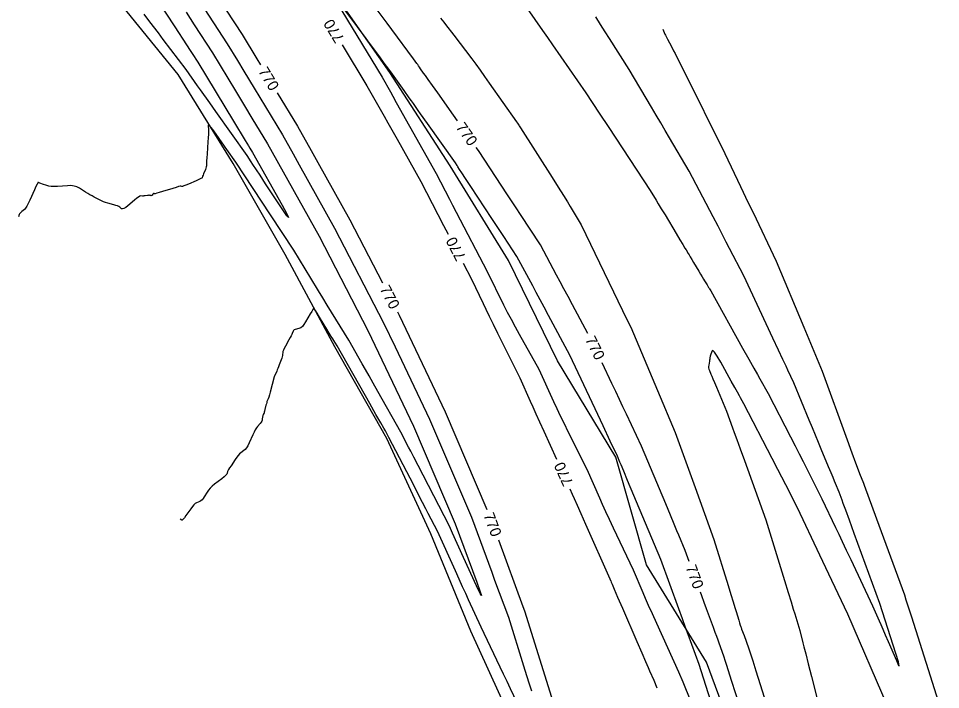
# Model space of a CAD drawing. Extents: x -26 to 1809989, y -25 to 828749.
# Drawn here: x 1809492.9 to 1809917.3, y 828203.8 to 828512.9 of the extents above; entities that cross this region are included whole.
import ezdxf

# ---------------------------------------------------------------- set-up
doc = ezdxf.new("R2010")
doc.units = 0
for name, color, linetype in [('DESIGN - CONTOURS - Index with Text', 7, 'Continuous'), ('DESIGN - CONTOURS - Intermediate with optional Text', 7, 'Continuous'), ('DESIGN - ROW - Slope Lines', 7, 'Continuous')]:
    doc.layers.add(name, color=color, linetype=linetype)

msp = doc.modelspace()

# ---------------------------------------------------------------- linework, layer by layer
at = {"layer": 'DESIGN - CONTOURS - Index with Text'}
for points in [[(1809549.23, 828574.97), (1809550.14, 828573.67), (1809554.39, 828567.6), (1809568.83, 828546.94), (1809584.94, 828522.18), (1809588.52, 828516.69), (1809595.77, 828505.55), (1809602.52, 828494.37), (1809604.26, 828491.5)], [(1809694.95, 828465.75), (1809693.1, 828468.36), (1809685.85, 828478.62), (1809683.41, 828482.08), (1809681.51, 828484.76), (1809680.17, 828486.66), (1809679.37, 828487.79), (1809677.98, 828489.76), (1809677.48, 828490.46), (1809677.03, 828491.1), (1809676.63, 828491.68), (1809676.27, 828492.18), (1809674.7, 828494.4), (1809664.78, 828507.8), (1809662.61, 828510.74), (1809660.36, 828513.79), (1809658.01, 828516.95), (1809655.58, 828520.24), (1809644.02, 828535.87), (1809638.31, 828543.4), (1809637.07, 828545.05), (1809635.97, 828546.5)], [(1809641.88, 828500.76), (1809653.29, 828481.93), (1809661.18, 828467.89), (1809662.91, 828464.8), (1809667.12, 828457.31), (1809678.07, 828437.79), (1809688.55, 828417.59), (1809690.67, 828413.5)], [(1809612.01, 828478.67), (1809621.31, 828463.29), (1809627.55, 828452.14), (1809630.69, 828446.52), (1809645.42, 828420.2), (1809660.41, 828391.19)], [(1809754.91, 828367.79), (1809747.87, 828381.02), (1809745.86, 828384.8), (1809743.97, 828388.35), (1809742.2, 828391.67), (1809740.55, 828394.76), (1809733.14, 828408.64), (1809723.96, 828422.63), (1809721.95, 828425.69), (1809719.85, 828428.89), (1809717.66, 828432.21), (1809715.39, 828435.66), (1809704.6, 828452.09), (1809703.6, 828453.5)], [(1809697.57, 828400.18), (1809701.37, 828392.86), (1809706.73, 828381.62), (1809708.01, 828378.96), (1809709.55, 828375.8), (1809711.35, 828372.14), (1809713.41, 828367.97), (1809723.63, 828347.38), (1809728.41, 828336.63), (1809729.57, 828334.04), (1809731, 828330.87), (1809732.71, 828327.12), (1809734.69, 828322.8), (1809740.59, 828309.93)], [(1809667.3, 828377.86), (1809668.09, 828376.33), (1809689.28, 828331.73), (1809708.53, 828286.78)], [(1809801.62, 828262.76), (1809799.73, 828267.94), (1809796.82, 828274.91), (1809795.97, 828276.93), (1809794.69, 828280), (1809792.97, 828284.12), (1809790.8, 828289.29), (1809779.69, 828315.87), (1809772.68, 828330.73), (1809771.14, 828334), (1809769.52, 828337.44), (1809767.82, 828341.05), (1809766.04, 828344.83), (1809761.55, 828354.35)], [(1809746.74, 828296.25), (1809747.76, 828293.88), (1809748.66, 828291.83), (1809749.98, 828288.82), (1809751.73, 828284.87), (1809753.91, 828279.96), (1809765.06, 828254.85), (1809765.29, 828254.31), (1809765.34, 828254.18), (1809765.41, 828254.02), (1809765.49, 828253.84), (1809765.72, 828253.31), (1809766.1, 828252.42), (1809767.09, 828250.12), (1809768.68, 828246.43), (1809770.88, 828241.33), (1809777.52, 828225.89), (1809779.76, 828220.71), (1809781.47, 828216.74), (1809782.67, 828213.99), (1809783.34, 828212.46), (1809785.29, 828208.16), (1809786.77, 828204.61)], [(1809713.76, 828272.72), (1809725.07, 828242.14), (1809725.84, 828240.05), (1809740.59, 828192.97), (1809743.73, 828180.77), (1809744.54, 828177.64)], [(1809837.62, 828153.6), (1809836.87, 828156.35), (1809836.16, 828159), (1809833.3, 828169.6), (1809823.06, 828201.85), (1809821.12, 828207.97), (1809819.69, 828212.48), (1809818.76, 828215.4), (1809818.35, 828216.71), (1809817.58, 828219.13), (1809815.38, 828225.13), (1809814.87, 828226.55), (1809814.26, 828228.22), (1809813.55, 828230.15), (1809812.75, 828232.34), (1809810.49, 828238.51), (1809809.58, 828241), (1809808.54, 828243.84), (1809807.37, 828247.04), (1809806.77, 828248.68)]]:
    msp.add_lwpolyline(points, dxfattribs=at)
at = {"layer": 'DESIGN - CONTOURS - Intermediate with optional Text'}
for points in [[(1809548.95, 828533.51), (1809564.88, 828509.02), (1809570.28, 828500.72), (1809571.91, 828498.22), (1809572.83, 828496.81), (1809575.44, 828492.79), (1809591.82, 828465.68), (1809597.22, 828456.75), (1809598.7, 828454.31), (1809599.36, 828453.2), (1809600.57, 828451.21), (1809614.18, 828426.89), (1809616.37, 828422.88), (1809617.12, 828421.26), (1809616.42, 828422.03), (1809614.27, 828425.2), (1809606.62, 828436.83), (1809604.06, 828440.72), (1809600.77, 828445.72), (1809600.05, 828446.82), (1809598.1, 828449.77), (1809583.76, 828470.07), (1809580.93, 828474.08), (1809576.72, 828480.02), (1809575.35, 828481.97), (1809570.08, 828489.42), (1809559.55, 828503.31), (1809557.3, 828506.27), (1809555.09, 828509.18), (1809552.91, 828512.06), (1809550.77, 828514.89)], [(1809572.03, 828527.36), (1809588.99, 828501.3), (1809593.71, 828493.49), (1809596.63, 828488.66), (1809601.33, 828480.87), (1809614.39, 828459.26), (1809619.28, 828450.54), (1809622.12, 828445.45), (1809638.38, 828416.4), (1809660.92, 828372.77), (1809666.2, 828361.66), (1809682, 828328.41), (1809701.33, 828283.27), (1809710.73, 828257.85), (1809712.06, 828254.25), (1809718.36, 828237.22), (1809725.38, 828214.76), (1809726.79, 828210.27), (1809727.99, 828206.44), (1809728.99, 828203.25)], [(1809821.84, 828166.13), (1809806.24, 828215.28), (1809801.17, 828229.14), (1809799.96, 828232.46), (1809798.51, 828236.4), (1809796.84, 828240.97), (1809788.52, 828263.71), (1809773.27, 828300.12), (1809771.46, 828304.43), (1809770.28, 828307.25), (1809769.72, 828308.57), (1809768.6, 828311.26), (1809765.28, 828318.29), (1809761.99, 828325.28), (1809759.5, 828330.55), (1809746.62, 828357.86), (1809736.88, 828376.11), (1809734.85, 828379.89), (1809731.21, 828386.7), (1809729.59, 828389.73), (1809722.34, 828403.27), (1809716.25, 828412.53), (1809712.94, 828417.55), (1809710.77, 828420.85), (1809701.08, 828435.57), (1809698.71, 828439.17), (1809697, 828441.78), (1809695.93, 828443.4), (1809695.16, 828444.57), (1809695.04, 828444.75), (1809694.9, 828444.96), (1809694.75, 828445.19), (1809693.98, 828446.36), (1809681.09, 828464.59), (1809677.93, 828469.04), (1809676.9, 828470.5), (1809674.64, 828473.7), (1809673.74, 828474.98), (1809672.72, 828476.41), (1809670.35, 828479.77), (1809664.28, 828488.33), (1809662.28, 828491.03), (1809661.74, 828491.77), (1809658.7, 828495.87), (1809653.65, 828502.69), (1809652.16, 828504.71), (1809650.58, 828506.83), (1809648.92, 828509.07), (1809641.31, 828519.36)], [(1809723.43, 828522.8), (1809734.15, 828507.37), (1809736.34, 828504.22), (1809738.74, 828500.76), (1809754.03, 828478.73), (1809760.2, 828469.38), (1809764.64, 828462.63), (1809783.68, 828433.73), (1809786.38, 828429.25), (1809787.38, 828427.59), (1809788.74, 828425.31), (1809790.48, 828422.42), (1809795.62, 828413.88), (1809797.35, 828411), (1809798.68, 828408.78), (1809799.63, 828407.2), (1809800.18, 828406.29), (1809801.13, 828404.7), (1809801.56, 828404), (1809802.12, 828403.06), (1809802.82, 828401.91), (1809803.65, 828400.52), (1809806.05, 828396.52), (1809806.89, 828395.12), (1809807.62, 828393.92), (1809808.22, 828392.92), (1809808.71, 828392.11), (1809809.86, 828390.21), (1809810.25, 828389.56), (1809810.56, 828389.04), (1809810.8, 828388.65), (1809810.96, 828388.38), (1809811.51, 828387.43), (1809826.2, 828361.1), (1809829.06, 828355.98), (1809831.34, 828351.91), (1809833.03, 828348.89), (1809834.14, 828346.91), (1809837.97, 828340.12), (1809848.22, 828320.24), (1809850.33, 828316.14), (1809852.27, 828312.35), (1809854.04, 828308.88), (1809855.65, 828305.72), (1809862.74, 828291.72), (1809868.99, 828278.49), (1809870.43, 828275.44), (1809872.08, 828271.96), (1809873.93, 828268.04), (1809875.98, 828263.69), (1809886.04, 828242.4), (1809889.03, 828235.5), (1809889.76, 828233.8), (1809890.7, 828231.64), (1809891.83, 828229.02), (1809893.16, 828225.95), (1809896.97, 828217.15), (1809898.02, 828214.88), (1809898.33, 828214.67), (1809897.88, 828216.53), (1809896.69, 828220.44), (1809889.36, 828243.53), (1809877.6, 828275.72), (1809875.36, 828281.86), (1809873.68, 828286.46), (1809872.55, 828289.53), (1809871.99, 828291.08), (1809870.66, 828294.71), (1809869.03, 828298.66), (1809868.56, 828299.78), (1809867.87, 828301.45), (1809866.95, 828303.67), (1809865.8, 828306.44), (1809862.43, 828314.56), (1809861.14, 828317.68), (1809859.78, 828320.96), (1809858.36, 828324.39), (1809856.88, 828327.97), (1809849.82, 828345.05), (1809847.07, 828350.9), (1809846.19, 828352.77), (1809844.75, 828355.85), (1809842.73, 828360.16), (1809840.14, 828365.7), (1809826.74, 828394.37), (1809820.19, 828407.01), (1809818.67, 828409.94), (1809816.91, 828413.34), (1809814.91, 828417.19), (1809812.67, 828421.49), (1809801.64, 828442.65), (1809792.59, 828457.98), (1809790.61, 828461.32), (1809788.57, 828464.78), (1809786.47, 828468.35), (1809784.29, 828472.03), (1809774.01, 828489.49), (1809764.98, 828503.69), (1809762.98, 828506.83), (1809760.86, 828510.17), (1809758.61, 828513.7)], [(1809570.02, 828515.78), (1809573.82, 828509.95), (1809582.22, 828497.04), (1809592.77, 828479.58), (1809596.92, 828472.71), (1809600.35, 828467.04), (1809607.48, 828455.23), (1809631.34, 828412.61), (1809653.76, 828369.21), (1809674.72, 828325.1), (1809693.95, 828280.2), (1809703.88, 828253.32), (1809705.46, 828248.89), (1809705.96, 828247.14), (1809705.37, 828248.04), (1809703.69, 828251.62), (1809697.75, 828264.71), (1809692.68, 828275.89), (1809691.23, 828279.07), (1809679.16, 828302.51), (1809676.8, 828307.09), (1809674.9, 828310.78), (1809673.45, 828313.59), (1809672.46, 828315.52), (1809668.89, 828322.44), (1809658.33, 828341.11), (1809656.18, 828344.9), (1809654.27, 828348.29), (1809652.58, 828351.26), (1809651.13, 828353.82), (1809644.9, 828364.81), (1809635.04, 828380.94), (1809632.99, 828384.31), (1809631.03, 828387.51), (1809627.45, 828393.38), (1809619.57, 828406.27), (1809608.87, 828422.53), (1809592.92, 828446.75), (1809588.76, 828452.63), (1809587.7, 828454.14), (1809582.77, 828461.1), (1809581.58, 828462.7), (1809580.75, 828463.65), (1809580.27, 828463.93), (1809580.14, 828463.56), (1809580.28, 828461.67), (1809580.31, 828460.79), (1809580.29, 828459.58), (1809580.21, 828458.02), (1809580.08, 828456.12), (1809579.67, 828450.6), (1809579.53, 828448.76), (1809579.44, 828447.38), (1809579.4, 828446.45), (1809579.4, 828445.98), (1809579.45, 828445.32), (1809579.43, 828445.02), (1809579.33, 828444.59), (1809579.15, 828444.03), (1809578.89, 828443.36), (1809578.08, 828441.38), (1809577.82, 828440.73), (1809577.63, 828440.24), (1809577.51, 828439.91), (1809577.46, 828439.75), (1809577.44, 828439.55), (1809577.27, 828439.41), (1809576.76, 828439.14), (1809575.91, 828438.74), (1809574.74, 828438.21), (1809571.15, 828436.63), (1809569.95, 828436.12), (1809569.05, 828435.77), (1809568.44, 828435.57), (1809568.12, 828435.54), (1809567.67, 828435.66), (1809567.3, 828435.63), (1809566.55, 828435.46), (1809565.4, 828435.13), (1809563.86, 828434.66), (1809559.22, 828433.19), (1809557.69, 828432.72), (1809556.57, 828432.39), (1809555.85, 828432.21), (1809555.55, 828432.17), (1809555.27, 828432.27), (1809555.17, 828432.28), (1809555.05, 828432.24), (1809554.92, 828432.15), (1809554.78, 828432.01), (1809554.39, 828431.57), (1809554.24, 828431.43), (1809554.09, 828431.34), (1809553.93, 828431.3), (1809553.76, 828431.32), (1809553.3, 828431.44), (1809553.11, 828431.48), (1809552.86, 828431.48), (1809552.57, 828431.46), (1809552.22, 828431.41), (1809551.23, 828431.24), (1809550.86, 828431.19), (1809550.52, 828431.16), (1809550.2, 828431.14), (1809549.89, 828431.14), (1809549.1, 828431.16), (1809548.7, 828431.04), (1809548.1, 828430.69), (1809547.29, 828430.09), (1809546.26, 828429.25), (1809543.27, 828426.69), (1809542.24, 828425.88), (1809541.42, 828425.38), (1809540.79, 828425.19), (1809540.35, 828425.31), (1809539.47, 828426.02), (1809539.05, 828426.29), (1809538.45, 828426.56), (1809537.68, 828426.84), (1809536.73, 828427.11), (1809533.98, 828427.84), (1809532.96, 828428.14), (1809531.97, 828428.5), (1809531.02, 828428.9), (1809530.1, 828429.36), (1809527.68, 828430.67), (1809526.76, 828431.18), (1809525.79, 828431.74), (1809524.79, 828432.34), (1809523.75, 828432.99), (1809520.93, 828434.79), (1809519.79, 828435.37), (1809518.49, 828435.74), (1809517.03, 828435.92), (1809515.4, 828435.9), (1809510.86, 828435.58), (1809509.27, 828435.52), (1809507.92, 828435.55), (1809506.8, 828435.68), (1809505.91, 828435.92), (1809503.86, 828436.68), (1809503.18, 828436.93), (1809502.68, 828437.12), (1809502.36, 828437.24), (1809502.22, 828437.29), (1809502.08, 828437.34), (1809502.03, 828437.36), (1809501.99, 828437.37), (1809501.96, 828437.38), (1809501.93, 828437.39), (1809501.85, 828437.41), (1809501.73, 828437.2), (1809501.42, 828436.55), (1809500.93, 828435.46), (1809500.24, 828433.93), (1809498.16, 828429.26), (1809497.41, 828427.68), (1809496.75, 828426.44), (1809496.16, 828425.54), (1809495.65, 828424.98), (1809494.39, 828423.94), (1809493.97, 828423.57), (1809493.64, 828423.24), (1809493.41, 828422.94), (1809493.27, 828422.69), (1809492.86, 828421.6)], [(1809641.77, 828516.37), (1809660.21, 828485.96), (1809664.08, 828479.06), (1809665.17, 828477.12), (1809666.78, 828474.25), (1809685.12, 828441.59), (1809691.3, 828429.66), (1809692.73, 828426.9), (1809694.38, 828423.72), (1809708.54, 828396.42), (1809716.18, 828381.03)], [(1809687.1, 828513.09), (1809687.85, 828512.2), (1809688.63, 828511.24), (1809689.44, 828510.21), (1809693.3, 828505.24), (1809701.55, 828494.27), (1809703.38, 828491.81), (1809705.33, 828489.14), (1809707.39, 828486.26), (1809709.57, 828483.17), (1809722.13, 828465.25), (1809722.54, 828464.66), (1809722.87, 828464.18), (1809723.13, 828463.8), (1809723.31, 828463.53), (1809723.96, 828462.52), (1809738.5, 828439.7), (1809741.36, 828435.2), (1809743.7, 828431.46), (1809745.54, 828428.51), (1809746.86, 828426.32), (1809751.84, 828417.92), (1809773.11, 828373.99), (1809774.72, 828370.66), (1809786.96, 828341.64), (1809795.12, 828322.29), (1809804.35, 828296.85), (1809813.02, 828272.96), (1809819.53, 828251.72), (1809820.81, 828247.56), (1809821.84, 828244.17), (1809822.65, 828241.55), (1809823.21, 828239.71), (1809824.4, 828235.82), (1809824.8, 828234.51), (1809825.12, 828233.49), (1809825.35, 828232.77), (1809825.49, 828232.35), (1809825.76, 828231.62), (1809826.13, 828230.61), (1809826.45, 828229.74), (1809826.85, 828228.65), (1809828.92, 828222.99), (1809829.51, 828221.12), (1809830.83, 828216.97), (1809832.28, 828212.39), (1809834.26, 828206.14), (1809844.75, 828173.07)], [(1809789.41, 828507.99), (1809790.46, 828505.76), (1809790.71, 828505.26), (1809790.99, 828504.69), (1809791.32, 828504.05), (1809791.68, 828503.36), (1809793.46, 828499.97), (1809794.46, 828498.05), (1809795.08, 828496.82), (1809796.51, 828493.94), (1809798.76, 828489.43), (1809817.98, 828450.77), (1809825.28, 828435.47), (1809828.83, 828428.03), (1809830.98, 828423.51), (1809841.64, 828401.16), (1809854.4, 828370.72), (1809855.92, 828367.1), (1809862.89, 828350.48), (1809874.34, 828318.86), (1809876.54, 828312.81), (1809878.22, 828308.22), (1809879.39, 828305.08), (1809880.04, 828303.4), (1809881.87, 828298.94), (1809882.22, 828297.97), (1809887.87, 828282.51), (1809900.7, 828247.38), (1809901.39, 828245.2), (1809903.88, 828237.35), (1809917.31, 828195.06)], [(1809726.91, 828188.32), (1809719.36, 828204.13), (1809717.75, 828207.5), (1809716.16, 828210.83), (1809714.58, 828214.12), (1809713.02, 828217.38), (1809705.79, 828232.48), (1809700.05, 828245.14), (1809698.75, 828248.01), (1809697.31, 828251.18), (1809695.73, 828254.65), (1809694.02, 828258.43), (1809685.69, 828276.76), (1809681.48, 828284.95), (1809680.38, 828287.08), (1809678.9, 828289.95), (1809677.04, 828293.56), (1809674.8, 828297.91), (1809663.43, 828319.95), (1809661.75, 828322.93), (1809661.03, 828324.2), (1809659.6, 828326.73), (1809657.44, 828330.52), (1809654.57, 828335.58), (1809639.51, 828362.14), (1809637.98, 828364.65), (1809637.54, 828365.38), (1809636.86, 828366.49), (1809635.95, 828367.98), (1809634.8, 828369.86), (1809631.43, 828375.36), (1809630.33, 828377.17), (1809629.53, 828378.46), (1809629.04, 828379.24), (1809628.86, 828379.5), (1809628.79, 828379.52), (1809628.67, 828379.35), (1809628.36, 828378.85), (1809627.86, 828378), (1809627.16, 828376.81), (1809625.05, 828373.19), (1809624.28, 828371.98), (1809623.57, 828371.08), (1809622.92, 828370.49), (1809622.31, 828370.2), (1809620.78, 828369.84), (1809620.26, 828369.67), (1809619.84, 828369.45), (1809619.53, 828369.17), (1809619.33, 828368.83), (1809618.92, 828367.85), (1809618.71, 828367.39), (1809618.39, 828366.74), (1809617.95, 828365.91), (1809617.4, 828364.9), (1809615.78, 828361.94), (1809615.25, 828360.93), (1809614.86, 828360.1), (1809614.62, 828359.47), (1809614.52, 828359.02), (1809614.47, 828358.08), (1809614.41, 828357.66), (1809614.27, 828357.11), (1809614.06, 828356.44), (1809613.78, 828355.64), (1809612.91, 828353.33), (1809612.59, 828352.5), (1809612.3, 828351.74), (1809612.02, 828351.06), (1809611.77, 828350.45), (1809610.62, 828347.79), (1809608.76, 828340.84), (1809608.39, 828339.51), (1809608.1, 828338.49), (1809607.87, 828337.79), (1809607.72, 828337.39), (1809607.39, 828336.76), (1809607.26, 828336.46), (1809607.12, 828336.03), (1809606.97, 828335.47), (1809606.81, 828334.79), (1809606.35, 828332.79), (1809606.19, 828332.11), (1809606.04, 828331.58), (1809605.91, 828331.2), (1809605.8, 828330.97), (1809605.53, 828330.55), (1809605.44, 828330.37), (1809605.36, 828330.11), (1809605.29, 828329.8), (1809605.24, 828329.42), (1809605.12, 828328.32), (1809605.02, 828327.9), (1809604.82, 828327.44), (1809604.52, 828326.94), (1809604.12, 828326.42), (1809602.9, 828324.97), (1809602.43, 828324.32), (1809601.9, 828323.46), (1809601.34, 828322.39), (1809600.72, 828321.11), (1809599.02, 828317.42), (1809598.4, 828316.15), (1809597.79, 828315.14), (1809597.21, 828314.38), (1809596.66, 828313.86), (1809595.21, 828312.82), (1809594.64, 828312.34), (1809594.03, 828311.69), (1809593.37, 828310.86), (1809592.66, 828309.85), (1809590.71, 828306.94), (1809590.07, 828305.94), (1809589.59, 828305.15), (1809589.28, 828304.57), (1809589.14, 828304.18), (1809588.99, 828303.43), (1809588.79, 828303.06), (1809588.3, 828302.52), (1809587.52, 828301.82), (1809586.44, 828300.95), (1809583.18, 828298.39), (1809582.05, 828297.45), (1809581.1, 828296.53), (1809580.33, 828295.65), (1809579.73, 828294.79), (1809578.39, 828292.55), (1809577.88, 828291.78), (1809577.36, 828291.17), (1809576.83, 828290.71), (1809576.29, 828290.41), (1809574.84, 828289.8), (1809574.27, 828289.46), (1809573.62, 828288.88), (1809572.91, 828288.08), (1809572.14, 828287.04), (1809569.98, 828283.96), (1809569.25, 828282.96), (1809568.69, 828282.27), (1809568.29, 828281.9), (1809568.05, 828281.83), (1809567.34, 828282.26)], [(1809716.18, 828381.03), (1809717.85, 828377.71), (1809719.6, 828374.35), (1809721.43, 828370.95), (1809723.33, 828367.51), (1809732.36, 828351.36), (1809739.17, 828336.51), (1809740.67, 828333.26), (1809742.28, 828329.88), (1809743.99, 828326.36), (1809745.79, 828322.71), (1809754.45, 828305.37), (1809760.27, 828292.2), (1809761.6, 828289.21), (1809763.11, 828285.89), (1809764.8, 828282.24), (1809766.67, 828278.26), (1809775.78, 828258.9), (1809780.27, 828248.47), (1809781.39, 828245.92), (1809782.8, 828242.72), (1809784.52, 828238.89), (1809786.53, 828234.41), (1809796.65, 828212.02), (1809798.61, 828207.32), (1809799.23, 828205.85), (1809801.62, 828200.1)], [(1809893.26, 828195.62), (1809874.64, 828238.52), (1809867.3, 828254.05), (1809861.74, 828265.79), (1809851.47, 828287.47), (1809846.04, 828298.05), (1809842.34, 828305.25), (1809839.79, 828310.21), (1809826.8, 828335.47), (1809825.26, 828338.22), (1809824.75, 828339.14), (1809823.86, 828340.72), (1809822.6, 828342.98), (1809820.97, 828345.9), (1809816.12, 828354.57), (1809814.51, 828357.34), (1809813.3, 828359.15), (1809812.5, 828360), (1809812.11, 828359.89), (1809811.6, 828358.32), (1809811.43, 828357.79), (1809811.31, 828357.39), (1809811.23, 828357.13), (1809811.2, 828357), (1809811.17, 828356.81), (1809811.16, 828356.74), (1809811.14, 828356.62), (1809811.13, 828356.56), (1809811.11, 828356.42), (1809811.09, 828356.29), (1809811.04, 828356.01), (1809810.97, 828355.58), (1809810.88, 828355), (1809810.6, 828353.27), (1809810.54, 828352.62), (1809810.57, 828351.97), (1809810.7, 828351.33), (1809810.92, 828350.7), (1809811.63, 828349.02), (1809811.98, 828348.18), (1809812.52, 828346.9), (1809813.24, 828345.2), (1809814.14, 828343.07), (1809818.75, 828332.12), (1809821.57, 828324.35), (1809822.36, 828322.17), (1809823.53, 828318.93), (1809825.08, 828314.64), (1809827.01, 828309.31), (1809836.89, 828281.97), (1809845.49, 828253.98), (1809847.17, 828248.53), (1809848.51, 828244.16), (1809849.51, 828240.88), (1809850.19, 828238.69), (1809852.54, 828231.01), (1809853.98, 828225.36), (1809854.45, 828223.48), (1809855.27, 828220.28), (1809856.42, 828215.74), (1809857.91, 828209.88), (1809865.64, 828179.4)]]:
    msp.add_lwpolyline(points, dxfattribs=at)
at = {"layer": 'DESIGN - ROW - Slope Lines'}
for p, q in [((1809663.79, 828488.05), (1809634.57, 828529.93)), ((1809566.33, 828487.06), (1809535.92, 828524.7)), ((1809591.76, 828446.07), (1809566.33, 828487.06)), ((1809691.61, 828445.09), (1809663.79, 828488.05)), ((1809615.63, 828404.15), (1809591.76, 828446.07)), ((1809718.51, 828401.37), (1809691.61, 828445.09)), ((1809638.52, 828361.65), (1809615.63, 828404.15)), ((1809740.94, 828355.27), (1809718.51, 828401.37)), ((1809662.4, 828319.48), (1809638.52, 828361.65)), ((1809767.8, 828310.92), (1809740.94, 828355.27)), ((1809682.72, 828275.53), (1809662.4, 828319.48)), ((1809782.02, 828261.25), (1809767.8, 828310.92)), ((1809701.14, 828230.72), (1809682.72, 828275.53)), ((1809809.5, 828216.39), (1809782.02, 828261.25)), ((1809721.26, 828186.4), (1809701.14, 828230.72)), ((1809827.77, 828167.92), (1809809.5, 828216.39))]:
    msp.add_line(p, q, dxfattribs=at)

# ---------------------------------------------------------------- texts
at = {"layer": 'DESIGN - CONTOURS - Index with Text'}
for rotation, p in [(121.2223, (1809643.06, 828503.63)), (301.1443, (1809603.07, 828488.63)), (305.2309, (1809693.97, 828462.81)), (117.4025, (1809698.94, 828402.97)), (297.3247, (1809659.04, 828388.4)), (296.2823, (1809753.61, 828365.1)), (114.1843, (1809748.32, 828298.98)), (290.3908, (1809706.84, 828284.19)), (290.0935, (1809799.91, 828260.17))]:
    msp.add_text('770', height=5, rotation=rotation, dxfattribs=at).set_placement(p)

doc.saveas('drawing.dxf')
